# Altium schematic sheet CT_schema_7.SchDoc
size 274 x 160 mm
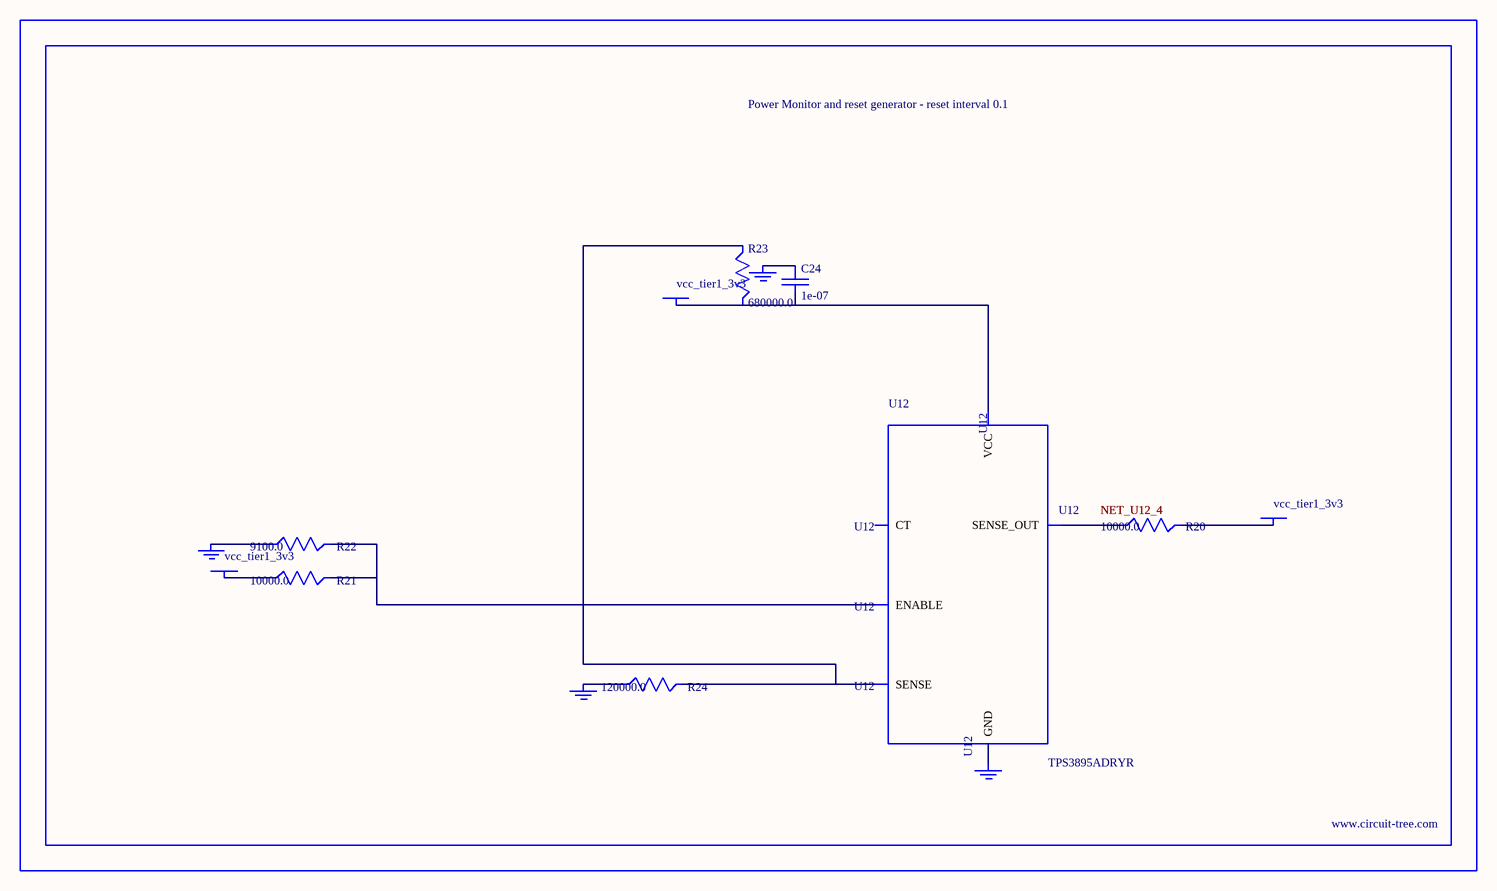
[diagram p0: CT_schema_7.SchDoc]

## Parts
BORDER6  (no value)
C24  1e-07  [C0402]
GND_INSTANCE_6_0  (no value)
GND_INSTANCE_6_1  (no value)
GND_INSTANCE_6_2  (no value)
GND_INSTANCE_6_3  (no value)
POWER_INSTANCE_6_0  vcc_tier1_3v3
POWER_INSTANCE_6_1  vcc_tier1_3v3
POWER_INSTANCE_6_2  vcc_tier1_3v3
R20  10000.0  [R0603]
R21  10000.0  [R0603]
R22  9100.0  [R0603]
R23  680000.0  [R0603]
R24  120000.0  [R0603]
U12  TPS3895ADRYR  [SON-6]

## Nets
NetC24_1: C24.1 GND_INSTANCE_6_2.0(GND)
NetC24_2: C24.2 POWER_INSTANCE_6_2.0(PWR) R23.2 U12.6(VCC)
NetGND_INSTANCE_6_0_0: GND_INSTANCE_6_0.0(GND) R22.1
NetGND_INSTANCE_6_1_0: GND_INSTANCE_6_1.0(GND) R24.1
NetGND_INSTANCE_6_3_0: GND_INSTANCE_6_3.0(GND) U12.2(GND)
NetPOWER_INSTANCE_6_0_0: POWER_INSTANCE_6_0.0(PWR) R21.1
NetPOWER_INSTANCE_6_1_0: POWER_INSTANCE_6_1.0(PWR) R20.2
NetR20_1: R20.1 U12.4(SENSE_OUT)
NetR21_2: R21.2 R22.2 U12.1(ENABLE)
NetR23_1: R23.1 R24.2 U12.3(SENSE)

Not connected (* = marked no-connect by the designer): U12 5(CT)

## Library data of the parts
BORDER6 = BORDER_PAGE6
C24 = C0402C104K3RACTU
GND_INSTANCE_6_0-GND_INSTANCE_6_3 = GND
POWER_INSTANCE_6_0-POWER_INSTANCE_6_2 = PWR
R20 R21 = RC0603JR-0710KL
R22 = RC0603JR-079K1L
R23 = RC0603JR-07680KL
R24 = RC0603JR-07120KL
